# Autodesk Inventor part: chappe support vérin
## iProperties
Created: 2002-05
Part Number: chappe support vérin
Material: Par défaut
Document SubType Name: Modélisation
Designer: REVEST Pierre
Control State: 0
Master: False
Checked Out: False
Shininess: 34.0
Length Units: 11269
Angle Units: 11279
Time Units: 11290
Mass Units: 11283
Length Display Precision: 3
Angle Display Precision: 2
Density: 0.0
Volumn: 0.0
Area: 0.0
PropertySet Name: Model Information
Author: REVEST Pierre
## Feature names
1. Extrusion1
2. Chanfrein1 [Chamfer]
3. Perçage1 [Hole]
4. Extrusion2
5. Extrusion3
6. Perçage2 [Hole]
7. Extrusion5
